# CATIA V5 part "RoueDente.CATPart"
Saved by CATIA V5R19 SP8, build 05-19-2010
Part number: engrenage1
Source: Unknown
Publications: "Esquisse.8", "Plan.3"
Material "Rouge DS": density 7860 kg/m3, Young's modulus 2e+11 Pa, Poisson ratio 0.266
Bounding box of the stored display mesh (mm): x 0 to 15, y -35.499 to 35.499, z -35.499 to 35.499
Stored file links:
  E:\EDELI\gcausse\Edeli_2012_184_gcausse\RoueDente.CATPart
  C:\usr\gt1\projet\site_web\doc\catia\gears\spur_gear_files\parts\gear_n.CATPart
  C:\Users\thinkmotion1\Desktop\Nouveau dossier\Cremai_Automobile\Cremaillere_automobile.CATProduct
  C:\Program Files\Dassault Systemes\B20\win_b64\startup\materials\French\Catalog.CATMaterial
  C:\Program Files\Dassault Systemes\B20\win_b64\startup\materials\red_env_512x512.jpg
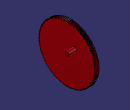
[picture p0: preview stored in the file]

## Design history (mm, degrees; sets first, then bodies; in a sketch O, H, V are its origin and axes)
Parameters
  a = 20 deg
  m = 0.5 mm
  Z = 140
  rp = 35 mm {= m * Z / 2}
  ra = 35.5 mm {= rp + m}
  rb = 32.8892 mm {= rp * cos( a )}
  rf = 34.375 mm {= rp - 1.25 * m}
  rc = 0.19 mm {= m * 0.38}
  c = 0.115855 {= sqrt( 1 / ( cos( a ) * cos( a ) ) - 1 ) / PI}
  phi = 1.4968 deg
  `diametre perçages extérieurs` = 35 mm
Set1
  DatumCurve1: linked copy from another document
Set2
  Line1 "Axe X": stored without definition
  Plane1: type Angle, RefPlane zx-plane, Direction Line1, Angle 1.2857 {= 180deg / Z}
  Point1 "origine": (0, 0, 0)
  Point2: (0, 0, 32.8892)
  Point3: (0, 0.3366, 34.4724)
  Point4: (0, 2.6135, 38.7545)
  Point5: (0, 8.3882, 44.4092)
  Point6: (0, 18.5079, 49.4703)
  Curve1: Elements (Point2; Point3; Point4; Point5; Point6)
  Extrapol1: ToExtrapol Point2, Support Curve1, Length 1 {= m * 2}
  Rotate1: Axis Line1, Angle 1.4968 {= phi}, ToTransfor Extrapol1
  Circle1: type CtrRad, Start 0, End 180, Center Point1, Support yz-plane, Radius 34.375 {= rf}, FirstDirection (0, 1, 0)
  Circle2: type CtrRad, Start 0, End 180, Center Point1, Support yz-plane, Radius 35.5 {= ra}, FirstDirection (0, 1, 0)
  Corner1: Element1 Rotate1, Element2 Circle1, Radius 0.19 {= rc}
  Symmetry1: Reference Plane1, ToTransfor Corner1
  Split1: ToCut Rotate1, Cutting (Corner1; Circle2)
  Symmetry2: Reference zx-plane, ToTransfor Split1
  Circle3: type 2PointsRad, Start 0, End 180, FirstPoint vertex of Symmetry1, SecondPoint vertex of Corner1, Support yz-plane, Radius 34.375 {= rf}
  Circle4: type 2PointsRad, Start 0, End 180, FirstPoint vertex of Split1, SecondPoint vertex of Symmetry2, Support yz-plane, Radius 35.5 {= ra}
  Join1: Elements (Symmetry1; Circle3; Corner1; Split1; Circle4; Symmetry2)
  CircPattern1: of Join1, instances 140 {= Z}, angular step 2.5714 {= 360.0*1 deg/CircPattern1.AngularNumber}, axis from Line1
  Join2: Elements (Join1; CircPattern1)
  Plane2: type Offset, RefPlane yz-plane, Offset 33
  Sketch1 on start face of Pad1, origin (0, 0, 0), H (0, -1, 0), V (0, 0, 1)
    circle A1 centre (0, 0) radius 2.5
    radius A1 = 2.5
Body1 (main body)
  Pad1: profile Join2, length 5
  Sketch2 on Plane2, origin (33, 0, 0), H (0, 1, 0), V (0, 0, 1)
    circle A1 centre (0, 0) radius 31.6677
    radius A1 = 31.6677
  Sketch3 on start face of Pad1, origin (0, 0, 0), H (0, -1, 0), V (0, 0, 1)
    circle A1 centre (0, 0) radius 10
    radius A1 = 10
  Sketch4 on end face of Pad1, origin (5, 0, 0), H (0, 1, 0), V (0, 0, 1)
    circle A1 centre (0, 0) radius 10
    radius A1 = 10
  Pocket1: profile Sketch1, direction (1, 0, 0), length 5
  Sketch5 on end face of Pad1, origin (5, 0, 0), H (0, 1, 0), V (0, 0, 1)
    circle A1 centre (10, 10) radius 2.5
    radius A1 = 2.5
  Pad2: profile Sketch5, direction (1, 0, 0), length 10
